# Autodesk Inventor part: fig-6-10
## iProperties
Created: 2004-05
Part Number: fig-6-10
Document SubType Name: Modeling
Designer: CADCIM Technologies
Manufacturer: Standard
Standards Organization: Custom
Density: 1 g/cm^3
Author: CADCIM Technologies
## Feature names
1. Extrusion1
2. Hole1
3. Circular Pattern1
